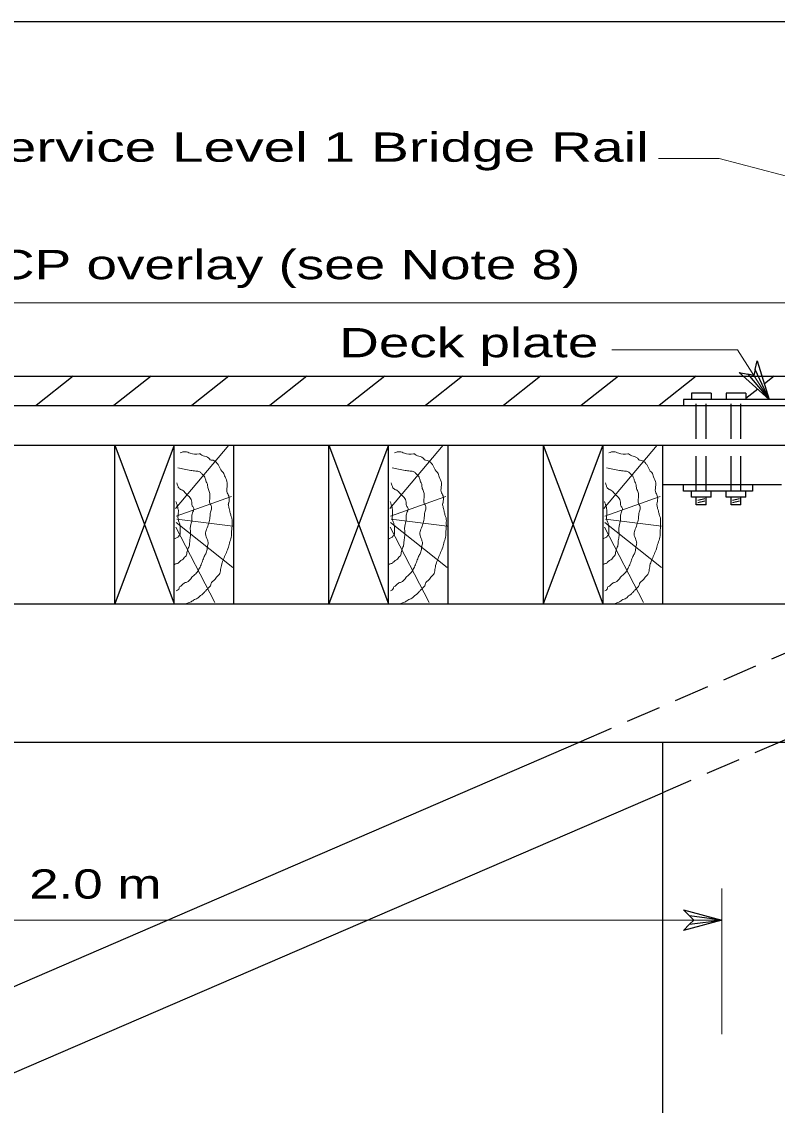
# Model space of a CAD drawing. Extents: x 13426 to 15509, y -9298 to -5111.
# Drawn here: x 15449.6 to 15483.31, y -5428.19 to -5379.81 of the extents above; entities that cross this region are included whole.
import ezdxf
from ezdxf.enums import TextEntityAlignment as Align

# ---------------------------------------------------------------- set-up
doc = ezdxf.new("R2010")
doc.units = 0
doc.header["$LTSCALE"] = 0.52
doc.linetypes.add('MEDIUM_DASHED', pattern=[4.5, 3, -1.5])
for name, color, linetype, lineweight in [('1', 7, 'Continuous', 13), ('15', 7, 'Continuous', 13), ('16', 7, 'Continuous', 25), ('2', 7, 'Continuous', 25), ('20', 7, 'Continuous', 13), ('30', 7, 'Continuous', 25), ('4', 7, 'Continuous', 13)]:
    doc.layers.add(name, color=color, linetype=linetype, lineweight=lineweight)
doc.layers.add('19', color=7, linetype='Continuous')

msp = doc.modelspace()

# ---------------------------------------------------------------- linework, layer by layer
at = {"layer": '1', "lineweight": 25}
for p, q in [((15363.992, -5405.801), (15491.456, -5405.801)), ((15491.456, -5411.997), (15381.02, -5411.997)), ((15478.179, -5411.997), (15478.179, -5453.953))]:
    msp.add_line(p, q, dxfattribs=at)
at = {"layer": '1'}
for p, q in [((15480.834, -5418.508), (15480.834, -5425.016)), ((15480.834, -5419.918), (15445.428, -5419.918))]:
    msp.add_line(p, q, dxfattribs=at)
at = {"layer": '15'}
for p, q in [((15486.643, -5392.358), (15368.805, -5392.358)), ((15481.531, -5394.465), (15475.93, -5394.465)), ((15482.95, -5396.673), (15481.531, -5394.465))]:
    msp.add_line(p, q, dxfattribs=at)
msp.add_lwpolyline([(15485.245, -5387.109), (15480.713, -5385.917), (15478, -5385.917)], dxfattribs=at)
at = {"layer": '16'}
for points in [[(15482.319, -5395.337), (15482.41, -5394.957), (15482.95, -5396.673), (15481.613, -5395.469), (15481.997, -5395.544), (15482.95, -5396.673), (15482.319, -5395.337), (15482.261, -5395.602), (15481.997, -5395.544)], [(15479.396, -5419.73), (15479.13, -5419.454), (15480.834, -5419.918), (15479.13, -5420.383), (15479.396, -5420.106), (15480.834, -5419.918), (15479.396, -5419.73), (15479.584, -5419.918), (15479.396, -5420.106)]]:
    msp.add_lwpolyline(points, dxfattribs=at)
at = {"layer": '2'}
for p, q in [((15480.358, -5396.396), (15479.473, -5396.396)), ((15479.473, -5396.396), (15479.473, -5396.673)), ((15480.358, -5396.396), (15480.358, -5396.673)), ((15481.907, -5396.396), (15481.022, -5396.396)), ((15481.022, -5396.396), (15481.022, -5396.673)), ((15481.907, -5396.396), (15481.907, -5396.673)), ((15479.473, -5401.043), (15479.473, -5400.767)), ((15480.358, -5401.043), (15479.473, -5401.043)), ((15479.694, -5401.375), (15479.694, -5401.043)), ((15480.072, -5401.112), (15479.764, -5401.188)), ((15480.137, -5401.375), (15480.137, -5401.043)), ((15480.358, -5401.043), (15480.358, -5400.767)), ((15481.022, -5401.043), (15481.022, -5400.767)), ((15481.907, -5401.043), (15481.022, -5401.043)), ((15481.243, -5401.375), (15481.243, -5401.043)), ((15481.622, -5401.112), (15481.313, -5401.188)), ((15481.686, -5401.375), (15481.686, -5401.043)), ((15481.907, -5401.043), (15481.907, -5400.767)), ((15480.137, -5401.375), (15479.694, -5401.375)), ((15480.074, -5401.214), (15479.766, -5401.291)), ((15481.686, -5401.375), (15481.243, -5401.375)), ((15481.623, -5401.214), (15481.315, -5401.291)), ((15448.083, -5423.379), (15474.434, -5411.997)), ((15448.083, -5427.235), (15478.179, -5414.237))]:
    msp.add_line(p, q, dxfattribs=at)
at = {"layer": '2', "linetype": 'MEDIUM_DASHED'}
for p, q in [((15479.694, -5400.767), (15479.694, -5396.673)), ((15480.137, -5400.767), (15480.137, -5396.673)), ((15481.243, -5400.767), (15481.243, -5396.673)), ((15481.686, -5400.767), (15481.686, -5396.673)), ((15488.78, -5405.801), (15474.434, -5411.997)), ((15490.184, -5409.051), (15478.179, -5414.237))]:
    msp.add_line(p, q, dxfattribs=at)
at = {"layer": '30'}
msp.add_line((15509.151, -5379.809), (15181.119, -5379.809), dxfattribs=at)
at = {"layer": '4', "lineweight": 25}
for p, q in [((15368.805, -5395.631), (15486.643, -5395.631)), ((15451.898, -5395.631), (15450.241, -5396.949)), ((15455.373, -5395.631), (15453.715, -5396.949)), ((15458.847, -5395.631), (15457.19, -5396.949)), ((15462.321, -5395.631), (15460.665, -5396.949)), ((15465.796, -5395.631), (15464.139, -5396.949)), ((15469.27, -5395.631), (15467.614, -5396.949)), ((15472.745, -5395.631), (15471.088, -5396.949)), ((15476.22, -5395.631), (15474.562, -5396.949)), ((15479.694, -5395.631), (15478.037, -5396.949)), ((15483.168, -5395.631), (15482.731, -5395.979)), ((15482.438, -5396.212), (15481.907, -5396.634)), ((15486.145, -5396.673), (15479.125, -5396.673)), ((15479.125, -5396.673), (15479.125, -5396.949)), ((15369.303, -5398.72), (15486.145, -5398.72)), ((15453.748, -5405.801), (15453.748, -5398.72)), ((15453.748, -5398.72), (15456.403, -5405.801)), ((15456.403, -5398.72), (15453.748, -5405.801)), ((15456.403, -5405.801), (15456.403, -5398.72)), ((15459.059, -5405.801), (15459.059, -5398.72)), ((15463.308, -5405.801), (15463.308, -5398.72)), ((15463.308, -5398.72), (15465.963, -5405.801)), ((15465.963, -5398.72), (15463.308, -5405.801)), ((15465.963, -5405.801), (15465.963, -5398.72)), ((15468.619, -5405.801), (15468.619, -5398.72)), ((15472.868, -5398.72), (15472.868, -5405.801)), ((15472.868, -5398.72), (15475.523, -5405.801)), ((15475.523, -5398.72), (15472.868, -5405.801)), ((15475.523, -5398.72), (15475.523, -5405.801)), ((15478.179, -5398.72), (15478.179, -5405.801)), ((15483.49, -5400.49), (15478.179, -5400.49)), ((15479.125, -5400.767), (15479.125, -5400.49)), ((15482.205, -5400.49), (15482.205, -5400.767)), ((15482.205, -5400.767), (15479.125, -5400.767))]:
    msp.add_line(p, q, dxfattribs=at)
at = {"layer": '4'}
for p, q in [((15458.834, -5398.719), (15456.456, -5401.539)), ((15468.394, -5398.719), (15466.016, -5401.539)), ((15477.954, -5398.719), (15475.575, -5401.539)), ((15458.966, -5401.013), (15456.489, -5401.879)), ((15468.525, -5401.013), (15466.048, -5401.879)), ((15478.085, -5401.013), (15475.608, -5401.879)), ((15459.015, -5402.337), (15456.521, -5402.015)), ((15468.575, -5402.337), (15466.081, -5402.015)), ((15478.134, -5402.337), (15475.641, -5402.015)), ((15458.211, -5405.735), (15456.472, -5402.372)), ((15459.015, -5404.172), (15456.489, -5402.168)), ((15467.771, -5405.735), (15466.032, -5402.372)), ((15468.575, -5404.172), (15466.048, -5402.168)), ((15477.331, -5405.735), (15475.592, -5402.372)), ((15478.134, -5404.172), (15475.608, -5402.168))]:
    msp.add_line(p, q, dxfattribs=at)
at = {"layer": '4', "lineweight": 25}
msp.add_lwpolyline([(15369.303, -5396.949), (15486.145, -5396.949), (15486.145, -5405.801)], dxfattribs=at)
at = {"layer": '4'}
for points in [[(15456.669, -5399.059), (15456.899, -5399.008), (15457.112, -5399.076), (15457.522, -5399.109), (15457.555, -5399.109), (15457.637, -5399.161), (15457.883, -5399.245), (15457.982, -5399.33), (15458.047, -5399.382), (15458.064, -5399.382), (15458.326, -5399.534), (15458.392, -5399.636), (15458.523, -5399.874), (15458.589, -5399.942), (15458.671, -5400.129), (15458.769, -5400.401), (15458.769, -5400.503), (15458.752, -5400.791), (15458.834, -5400.979), (15458.851, -5401.149), (15458.834, -5401.284), (15458.818, -5401.335), (15458.818, -5401.386), (15458.834, -5401.454), (15458.851, -5401.539), (15458.883, -5401.658), (15458.9, -5401.743), (15458.949, -5401.896), (15458.982, -5402.032), (15458.982, -5402.151), (15458.982, -5402.337), (15458.966, -5402.542), (15458.949, -5402.83), (15458.867, -5403.085), (15458.802, -5403.34), (15458.703, -5403.561), (15458.605, -5403.799), (15458.523, -5404.019), (15458.473, -5404.274), (15458.408, -5404.495), (15458.293, -5404.614), (15458.162, -5404.767), (15458.047, -5404.886), (15458.031, -5404.954), (15457.998, -5405.022), (15457.932, -5405.09), (15457.834, -5405.192), (15457.752, -5405.277), (15457.653, -5405.379), (15457.555, -5405.447), (15457.44, -5405.549), (15457.26, -5405.634), (15457.194, -5405.685), (15457.112, -5405.719), (15457.03, -5405.753), (15456.882, -5405.804), (15456.881, -5405.804)], [(15466.229, -5399.059), (15466.459, -5399.008), (15466.672, -5399.076), (15467.082, -5399.109), (15467.115, -5399.109), (15467.197, -5399.161), (15467.443, -5399.245), (15467.541, -5399.33), (15467.607, -5399.382), (15467.623, -5399.382), (15467.886, -5399.534), (15467.952, -5399.636), (15468.082, -5399.874), (15468.148, -5399.942), (15468.23, -5400.129), (15468.329, -5400.401), (15468.329, -5400.503), (15468.312, -5400.791), (15468.394, -5400.979), (15468.411, -5401.149), (15468.394, -5401.284), (15468.378, -5401.335), (15468.378, -5401.386), (15468.394, -5401.454), (15468.411, -5401.539), (15468.443, -5401.658), (15468.46, -5401.743), (15468.509, -5401.896), (15468.542, -5402.032), (15468.542, -5402.151), (15468.542, -5402.337), (15468.525, -5402.542), (15468.509, -5402.83), (15468.427, -5403.085), (15468.361, -5403.34), (15468.263, -5403.561), (15468.164, -5403.799), (15468.082, -5404.019), (15468.034, -5404.274), (15467.968, -5404.495), (15467.853, -5404.614), (15467.722, -5404.767), (15467.607, -5404.886), (15467.591, -5404.954), (15467.558, -5405.022), (15467.492, -5405.09), (15467.394, -5405.192), (15467.312, -5405.277), (15467.213, -5405.379), (15467.115, -5405.447), (15467, -5405.549), (15466.819, -5405.634), (15466.754, -5405.685), (15466.672, -5405.719), (15466.59, -5405.753), (15466.442, -5405.804), (15466.441, -5405.804)], [(15475.789, -5399.059), (15476.018, -5399.008), (15476.232, -5399.076), (15476.642, -5399.109), (15476.675, -5399.109), (15476.757, -5399.161), (15477.002, -5399.245), (15477.101, -5399.33), (15477.167, -5399.382), (15477.183, -5399.382), (15477.445, -5399.534), (15477.511, -5399.636), (15477.642, -5399.874), (15477.708, -5399.942), (15477.79, -5400.129), (15477.888, -5400.401), (15477.888, -5400.503), (15477.872, -5400.791), (15477.954, -5400.979), (15477.97, -5401.149), (15477.954, -5401.284), (15477.938, -5401.335), (15477.938, -5401.386), (15477.954, -5401.454), (15477.97, -5401.539), (15478.003, -5401.658), (15478.02, -5401.743), (15478.069, -5401.896), (15478.102, -5402.032), (15478.102, -5402.151), (15478.102, -5402.337), (15478.085, -5402.542), (15478.069, -5402.83), (15477.987, -5403.085), (15477.921, -5403.34), (15477.823, -5403.561), (15477.724, -5403.799), (15477.642, -5404.019), (15477.593, -5404.274), (15477.527, -5404.495), (15477.413, -5404.614), (15477.281, -5404.767), (15477.167, -5404.886), (15477.15, -5404.954), (15477.118, -5405.022), (15477.052, -5405.09), (15476.954, -5405.192), (15476.872, -5405.277), (15476.773, -5405.379), (15476.675, -5405.447), (15476.56, -5405.549), (15476.379, -5405.634), (15476.314, -5405.685), (15476.232, -5405.719), (15476.15, -5405.753), (15476.002, -5405.804), (15476.001, -5405.804)], [(15456.571, -5399.721), (15456.849, -5399.789), (15457.145, -5399.84), (15457.243, -5399.857), (15457.374, -5399.874), (15457.424, -5399.874), (15457.571, -5399.925), (15457.588, -5399.942), (15457.67, -5400.027), (15457.785, -5400.197), (15457.834, -5400.35), (15457.883, -5400.452), (15457.9, -5400.605), (15457.965, -5400.791), (15457.998, -5400.961), (15457.982, -5401.182), (15457.998, -5401.318), (15458.064, -5401.454), (15458.064, -5401.573), (15458.014, -5401.76), (15457.998, -5401.93), (15457.85, -5402.473), (15457.801, -5402.677), (15457.883, -5402.949), (15457.916, -5403.085), (15457.883, -5403.255), (15457.85, -5403.476), (15457.768, -5403.646), (15457.686, -5403.833), (15457.604, -5404.053), (15457.555, -5404.156), (15457.456, -5404.343), (15457.325, -5404.495), (15457.194, -5404.614), (15456.964, -5404.835), (15456.899, -5404.852), (15456.833, -5404.886), (15456.784, -5404.92), (15456.735, -5404.988), (15456.62, -5405.073), (15456.62, -5405.107), (15456.571, -5405.175), (15456.554, -5405.192), (15456.489, -5405.226)], [(15466.13, -5399.721), (15466.409, -5399.789), (15466.705, -5399.84), (15466.803, -5399.857), (15466.934, -5399.874), (15466.984, -5399.874), (15467.131, -5399.925), (15467.148, -5399.942), (15467.23, -5400.027), (15467.345, -5400.197), (15467.394, -5400.35), (15467.443, -5400.452), (15467.459, -5400.605), (15467.525, -5400.791), (15467.558, -5400.961), (15467.541, -5401.182), (15467.558, -5401.318), (15467.623, -5401.454), (15467.623, -5401.573), (15467.574, -5401.76), (15467.558, -5401.93), (15467.41, -5402.473), (15467.361, -5402.677), (15467.443, -5402.949), (15467.476, -5403.085), (15467.443, -5403.255), (15467.41, -5403.476), (15467.328, -5403.646), (15467.246, -5403.833), (15467.164, -5404.053), (15467.115, -5404.156), (15467.016, -5404.343), (15466.885, -5404.495), (15466.754, -5404.614), (15466.524, -5404.835), (15466.459, -5404.852), (15466.393, -5404.886), (15466.344, -5404.92), (15466.294, -5404.988), (15466.18, -5405.073), (15466.18, -5405.107), (15466.13, -5405.175), (15466.114, -5405.192), (15466.048, -5405.226)], [(15475.69, -5399.721), (15475.969, -5399.789), (15476.264, -5399.84), (15476.363, -5399.857), (15476.494, -5399.874), (15476.543, -5399.874), (15476.691, -5399.925), (15476.707, -5399.942), (15476.79, -5400.027), (15476.904, -5400.197), (15476.954, -5400.35), (15477.002, -5400.452), (15477.019, -5400.605), (15477.085, -5400.791), (15477.118, -5400.961), (15477.101, -5401.182), (15477.118, -5401.318), (15477.183, -5401.454), (15477.183, -5401.573), (15477.134, -5401.76), (15477.118, -5401.93), (15476.97, -5402.473), (15476.921, -5402.677), (15477.002, -5402.949), (15477.036, -5403.085), (15477.002, -5403.255), (15476.97, -5403.476), (15476.888, -5403.646), (15476.806, -5403.833), (15476.724, -5404.053), (15476.675, -5404.156), (15476.576, -5404.343), (15476.445, -5404.495), (15476.314, -5404.614), (15476.084, -5404.835), (15476.018, -5404.852), (15475.953, -5404.886), (15475.904, -5404.92), (15475.854, -5404.988), (15475.739, -5405.073), (15475.739, -5405.107), (15475.69, -5405.175), (15475.674, -5405.192), (15475.608, -5405.226)], [(15456.521, -5400.401), (15456.554, -5400.503), (15456.603, -5400.622), (15456.719, -5400.706), (15456.767, -5400.724), (15456.849, -5400.791), (15456.964, -5400.928), (15457.063, -5401.013), (15457.128, -5401.097), (15457.178, -5401.199), (15457.21, -5401.42), (15457.276, -5401.539), (15457.26, -5401.641), (15457.194, -5401.845), (15457.194, -5402.049), (15457.128, -5402.337), (15457.128, -5402.762), (15457.096, -5402.983), (15457.079, -5403.187), (15457.014, -5403.357), (15456.964, -5403.561), (15456.931, -5403.663), (15456.866, -5403.714), (15456.8, -5403.799), (15456.603, -5403.952), (15456.554, -5404.003), (15456.521, -5404.003), (15456.407, -5404.053)], [(15466.081, -5400.401), (15466.114, -5400.503), (15466.163, -5400.622), (15466.278, -5400.706), (15466.327, -5400.724), (15466.409, -5400.791), (15466.524, -5400.928), (15466.623, -5401.013), (15466.688, -5401.097), (15466.737, -5401.199), (15466.77, -5401.42), (15466.836, -5401.539), (15466.819, -5401.641), (15466.754, -5401.845), (15466.754, -5402.049), (15466.688, -5402.337), (15466.688, -5402.762), (15466.655, -5402.983), (15466.639, -5403.187), (15466.573, -5403.357), (15466.524, -5403.561), (15466.491, -5403.663), (15466.426, -5403.714), (15466.36, -5403.799), (15466.163, -5403.952), (15466.114, -5404.003), (15466.081, -5404.003), (15465.966, -5404.053)], [(15475.641, -5400.401), (15475.674, -5400.503), (15475.723, -5400.622), (15475.838, -5400.706), (15475.887, -5400.724), (15475.969, -5400.791), (15476.084, -5400.928), (15476.182, -5401.013), (15476.248, -5401.097), (15476.297, -5401.199), (15476.33, -5401.42), (15476.396, -5401.539), (15476.379, -5401.641), (15476.314, -5401.845), (15476.314, -5402.049), (15476.248, -5402.337), (15476.248, -5402.762), (15476.215, -5402.983), (15476.199, -5403.187), (15476.133, -5403.357), (15476.084, -5403.561), (15476.051, -5403.663), (15475.986, -5403.714), (15475.92, -5403.799), (15475.723, -5403.952), (15475.674, -5404.003), (15475.641, -5404.003), (15475.526, -5404.053)], [(15456.472, -5401.233), (15456.521, -5401.352), (15456.538, -5401.42), (15456.571, -5401.488), (15456.571, -5401.556), (15456.587, -5401.624), (15456.587, -5401.675), (15456.587, -5401.743), (15456.571, -5401.913), (15456.587, -5402.066), (15456.636, -5402.202), (15456.669, -5402.355), (15456.669, -5402.661), (15456.653, -5402.728), (15456.636, -5402.728), (15456.603, -5402.796), (15456.505, -5402.847), (15456.44, -5402.881), (15456.39, -5402.915)], [(15466.032, -5401.233), (15466.081, -5401.352), (15466.098, -5401.42), (15466.13, -5401.488), (15466.13, -5401.556), (15466.147, -5401.624), (15466.147, -5401.675), (15466.147, -5401.743), (15466.13, -5401.913), (15466.147, -5402.066), (15466.196, -5402.202), (15466.229, -5402.355), (15466.229, -5402.661), (15466.212, -5402.728), (15466.196, -5402.728), (15466.163, -5402.796), (15466.065, -5402.847), (15465.999, -5402.881), (15465.95, -5402.915)], [(15475.592, -5401.233), (15475.641, -5401.352), (15475.657, -5401.42), (15475.69, -5401.488), (15475.69, -5401.556), (15475.707, -5401.624), (15475.707, -5401.675), (15475.707, -5401.743), (15475.69, -5401.913), (15475.707, -5402.066), (15475.756, -5402.202), (15475.789, -5402.355), (15475.789, -5402.661), (15475.772, -5402.728), (15475.756, -5402.728), (15475.723, -5402.796), (15475.625, -5402.847), (15475.559, -5402.881), (15475.51, -5402.915)]]:
    msp.add_spline(points, degree=3, dxfattribs=at)

# ---------------------------------------------------------------- texts
at = {"layer": '19', "width": 1.35}
msp.add_text('2.0 m', height=1.307, dxfattribs=at).set_placement((15452.8835, -5418.961), align=Align.CENTER)
at = {"layer": '20'}
for s, width, p in [('Service Level 1 Bridge Rail', 1.45, (15477.578, -5386.063)), ('Deck plate', 1.4, (15475.325, -5394.792))]:
    msp.add_text(s, height=1.307, dxfattribs=dict(at, width=width)).set_placement(p, align=Align.RIGHT)
at = {"layer": '20', "width": 1.4}
msp.add_text('ACP overlay (see Note 8)', height=1.307, dxfattribs=at).set_placement((15446.778, -5391.308))

doc.saveas('drawing.dxf')
